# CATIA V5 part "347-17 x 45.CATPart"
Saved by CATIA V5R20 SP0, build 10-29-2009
Part number: 347-17 x 45
Definition: NONE
Nomenclature: 347-17 x 45
Source: Unknown
Description: 347-17 x 45
Bounding box of the stored display mesh (mm): x 0 to 45, y -14 to 14, z -14 to 14
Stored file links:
  C:\Users\Utente\Desktop\IO LAVORO\3D X SITO CF\X SITO\3D files 347\347-17 x 45.CATPart
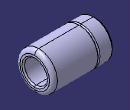
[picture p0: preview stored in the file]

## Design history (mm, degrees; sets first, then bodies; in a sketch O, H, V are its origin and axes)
Body1 "347-17 x 45" (main body)
  Solid1: solid without history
